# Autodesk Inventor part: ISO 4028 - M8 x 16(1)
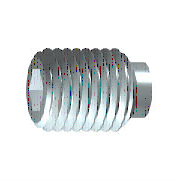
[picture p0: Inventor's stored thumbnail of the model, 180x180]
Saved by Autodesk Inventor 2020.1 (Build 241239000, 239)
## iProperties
Created: 2019-01
Part Number: ISO 4028 - M8 x 16(1)
Material: Edelstahl, 440C
Description: Innensechskant-Gewindestifte mit Zapfen
Document SubType Name: Modeling
Standard: ISO 4028
Designer: lutzd
Standard Revision: Third edition 2003-12-01
Standards Organization: ISO
Language: de-DE
Size Designation: M8 x 16
Categories: <MemberInstance><Categories><Category DisplayName="Verbindungselemente" InternalName="e4da775c-781d-43d5-af7c-5136215cf5a6" Mnemonic="FSTN"><Category DisplayNam
Mass: 4.62821 g
Surface Area: 5.118 cm^2
Volume: 0.597188 cm^3
Density: 7.75 g/cm^3
Appearance: Halbpoliert
IsCustomPart: 0
Author: lutzd
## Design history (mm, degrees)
sketch "Skizze1"
  geometry: L1 (0, 0)-(9.667, 0); L2 (16, 2.309)-(16, 4); L3 (16, 4)-(4, 4); L4 (16, 2.309)-(11, 2.309); L5 (11, 2.309)-(9.667, 0); L6 (0, -0.8)-(0, 4.8) reference; L7 (0, 2.75)-(0, 0); L8 (0, 2.75)-(4, 2.75); L9 (4, 2.75)-(4, 4)
  constraints: 17 end point, 3 parallel, 3 perpendicular, 1 collinear, 1 point on line
  dimensions: "d0" = 5 distance of L2.start L4.end (= INTI); "d1" = 60 deg angle of L5 L1; "d2" = 8 diameter of L3 L1 (= NND); "d3" = 4.6188 diameter of L4 L1 (= 1.1547 x SW); "d5" = 16 distance from line of L2 L7.start (= NLG); "d7" = 5.5 diameter of L7.start L1 (= SPD); "d14" = 4 distance of L7.start L8.end (= ZLG)
revolve "Körper" sketch "Skizze1" stored, may be unused: angle "d6" = 90 deg
sketch "Skizze2"
  geometry: L1 (-1.155, 2)-(1.155, 2); L2 (1.155, 2)-(2.309, 0); L3 (2.309, 0)-(1.155, -2); L4 (1.155, -2)-(-1.155, -2); L5 (-1.155, -2)-(-2.309, 0); L6 (-2.309, 0)-(-1.155, 2); A1 r 2.309 centre (0, 0) between (-1.155, 2) and (1.155, 2) reference; 2 further points
  constraints: 12 end point, 2 point on circle, 1 coincident, 1 horizontal, 11 other
extrude "Loch" join sketch "Skizze2" taper "d10" = 0 deg; stored distance "d21" = 10
workaxis "Work Axis1"
workplane "Work Plane1"
body "Solid1"
chamfer "Fase1" distance "d8" = 0.76681 (computed from NND, GD1, FAWI); stored, may be unused: angle "d9" = 45 deg (= FAWI), second distance "d30" = 0.76681 (computed from NND, GD1, FAWI)
feature "Gewinde" dims "d12" = 12 (= NLG - ZLG), "d13" = 0
chamfer "Fase2" distance "d15" = 1.25 (computed from NND, SPD, FAWI1); stored, may be unused: angle "d16" = 45 deg (= FAWI1), second distance "d31" = 1.25 (computed from NND, SPD, FAWI1)
other parameters: "NND" = 8 [user parameter; used in 5 equation terms], "NLG" = 16 [user parameter; used in 2 equation terms], "INTI" = 5 [user parameter; used in 1 equation term], "FAWI" = 45 deg [user parameter; used in 3 equation terms], "SW" = 4 [user parameter; used in 2 equation terms], "GD1" = 6.46637 (= THREADDIA - 1.2269 x PTC) [user parameter; used in 2 equation terms], "d4" = 0, "FAWI1" = 45 deg [user parameter; used in 3 equation terms], "SPD" = 5.5 [user parameter; used in 3 equation terms], "ZLG" = 4 [user parameter; used in 2 equation terms], "d32" = 0, "d33" = 0, "GUL" = 0.76681 (= 0.61345 x PTC) [user parameter], "TPU" = 8 (computed from PTC) [user parameter], "TOA" = 30 deg [user parameter], "THREADDIA" = 8 [user parameter; used in 1 equation term], "PTC" = 1.25 [user parameter; used in 4 equation terms], "GAL" = 0.76681 (= 0.61345 x PTC) [user parameter], "E0" = 4.62 (= 1.155 x SW) [user parameter]
